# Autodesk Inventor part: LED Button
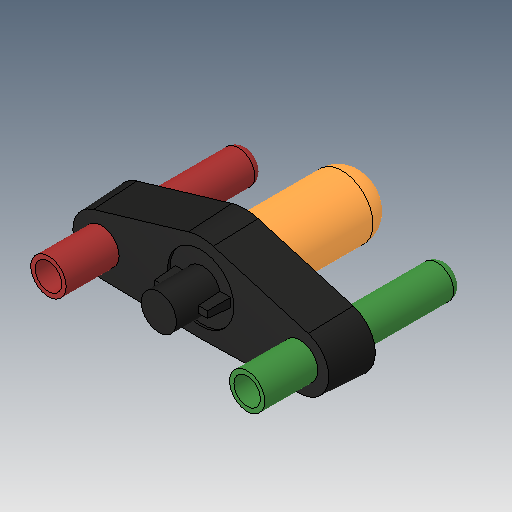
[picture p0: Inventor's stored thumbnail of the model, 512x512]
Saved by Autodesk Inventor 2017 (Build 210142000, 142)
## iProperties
Created: 2006-01
Part Number: LED Button
Material: Generic
Document SubType Name: Modeling
Designer: DanielSeverino
Density: 1 g/cm^3
Appearance: Default
Author: DanielSeverino
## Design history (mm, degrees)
feature "Solid1"
body "Solid2"
